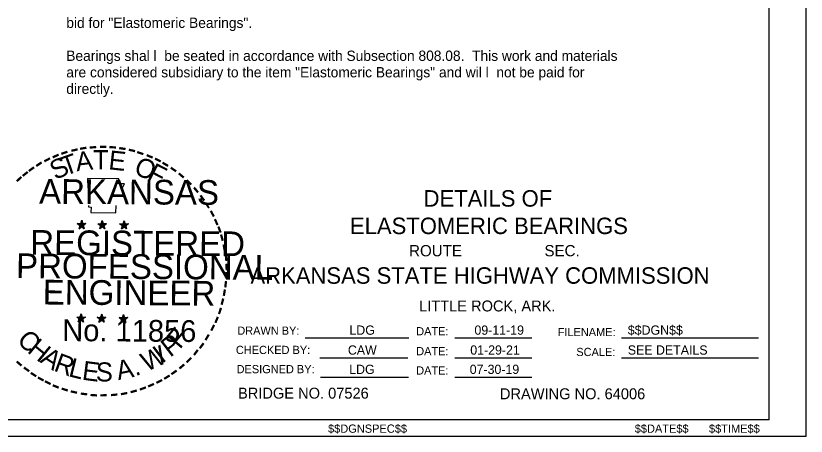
# Model space of a CAD drawing. Extents: x 32334 to 32601, y -901 to -733.
# Drawn here: x 32524.1 to 32600.8, y -900.6 to -859.7 of the extents above; entities that cross this region are included whole.
import ezdxf

# ---------------------------------------------------------------- set-up
doc = ezdxf.new("R2010")
doc.units = 0
for name, color, linetype in [('1', 7, 'Continuous'), ('Level 1', 7, 'Continuous'), ('Level 4', 7, 'Continuous'), ('Level 48', 7, 'Continuous'), ('Level 49', 7, 'Continuous'), ('Level 50', 7, 'Continuous'), ('Level 63', 7, 'Continuous')]:
    doc.layers.add(name, color=color, linetype=linetype)

msp = doc.modelspace()

# ---------------------------------------------------------------- linework, layer by layer
at = {"layer": 'Level 1'}
for q in [(32597.248, -734.586), (32344.303, -898.954)]:
    msp.add_line((32597.248, -898.954), q, dxfattribs=at)
at = {"layer": 'Level 4'}
for p, q in [((32552.203, -891.002), (32562.264, -891.002)), ((32566.721, -891.002), (32574.208, -891.002)), ((32582.925, -891.002), (32596.204, -891.002)), ((32553.623, -892.935), (32562.179, -892.935)), ((32566.721, -892.935), (32574.208, -892.935)), ((32582.925, -892.935), (32596.204, -892.935)), ((32553.683, -894.809), (32562.238, -894.809)), ((32566.721, -894.809), (32574.208, -894.809))]:
    msp.add_line(p, q, dxfattribs=at)
at = {"layer": 'Level 49'}
for p, q in [((32530.079, -879.921), (32530.508, -880.054)), ((32530.079, -879.921), (32530.39, -879.936)), ((32530.079, -879.921), (32530.39, -879.951)), ((32530.079, -879.921), (32530.36, -879.995)), ((32530.079, -879.921), (32530.36, -880.039)), ((32530.079, -879.921), (32530.36, -880.054)), ((32530.079, -879.921), (32530.36, -880.099)), ((32530.256, -880.409), (32530.508, -880.054)), ((32530.256, -880.409), (32530.36, -880.069)), ((32530.256, -880.409), (32530.39, -880.113)), ((32530.256, -880.409), (32530.404, -880.128)), ((32530.256, -880.409), (32530.449, -880.158)), ((32530.256, -880.409), (32530.508, -880.158)), ((32530.508, -879.595), (32530.449, -879.921)), ((32530.508, -879.595), (32530.449, -879.891)), ((32530.508, -879.595), (32530.478, -879.891)), ((32530.508, -880.054), (32530.508, -879.595)), ((32530.508, -879.595), (32530.582, -879.921)), ((32530.508, -879.595), (32530.567, -879.891)), ((32530.508, -879.595), (32530.523, -879.891)), ((32530.922, -879.921), (32530.508, -880.054)), ((32530.76, -880.424), (32530.508, -880.054)), ((32530.76, -880.424), (32530.508, -880.158)), ((32530.922, -879.921), (32530.538, -879.951)), ((32530.76, -880.424), (32530.538, -880.158)), ((32530.922, -879.921), (32530.582, -879.98)), ((32530.922, -879.921), (32530.582, -880.01)), ((32530.76, -880.424), (32530.582, -880.069)), ((32530.76, -880.424), (32530.582, -880.113)), ((32530.76, -880.424), (32530.626, -880.054)), ((32530.922, -879.921), (32530.641, -880.01)), ((32530.922, -879.921), (32530.686, -880.039)), ((32530.922, -879.921), (32530.7, -880.054)), ((32532.077, -879.936), (32532.506, -880.054)), ((32532.077, -879.936), (32532.388, -879.951)), ((32532.077, -879.936), (32532.388, -879.98)), ((32532.077, -879.936), (32532.388, -879.995)), ((32532.077, -879.936), (32532.373, -880.054)), ((32532.077, -879.936), (32532.373, -880.069)), ((32532.077, -879.936), (32532.373, -880.113)), ((32532.254, -880.424), (32532.506, -880.054)), ((32532.254, -880.424), (32532.388, -880.099)), ((32532.254, -880.424), (32532.388, -880.113)), ((32532.254, -880.424), (32532.402, -880.128)), ((32532.254, -880.424), (32532.447, -880.173)), ((32532.254, -880.424), (32532.506, -880.173)), ((32532.506, -879.625), (32532.447, -879.936)), ((32532.506, -879.625), (32532.447, -879.921)), ((32532.506, -879.625), (32532.462, -879.921)), ((32532.506, -880.054), (32532.506, -879.625)), ((32532.506, -879.625), (32532.58, -879.936)), ((32532.506, -879.625), (32532.565, -879.921)), ((32532.506, -879.625), (32532.521, -879.921)), ((32532.92, -879.936), (32532.506, -880.054)), ((32532.758, -880.424), (32532.506, -880.054)), ((32532.758, -880.424), (32532.506, -880.173)), ((32532.92, -879.936), (32532.55, -879.951)), ((32532.758, -880.424), (32532.55, -880.173)), ((32532.92, -879.936), (32532.58, -879.995)), ((32532.92, -879.936), (32532.58, -880.01)), ((32532.758, -880.424), (32532.58, -880.069)), ((32532.758, -880.424), (32532.58, -880.128)), ((32532.758, -880.424), (32532.624, -880.069)), ((32532.92, -879.936), (32532.639, -880.039)), ((32532.92, -879.936), (32532.684, -880.054)), ((32532.92, -879.936), (32532.698, -880.069)), ((32534.193, -879.951), (32534.623, -880.099)), ((32534.193, -879.951), (32534.534, -879.995)), ((32534.193, -879.951), (32534.504, -880.01)), ((32534.193, -879.951), (32534.504, -880.039)), ((32534.193, -879.951), (32534.489, -880.069)), ((32534.193, -879.951), (32534.489, -880.113)), ((32534.193, -879.951), (32534.489, -880.113)), ((32534.356, -880.439), (32534.623, -880.099)), ((32534.356, -880.439), (32534.504, -880.113)), ((32534.356, -880.439), (32534.534, -880.158)), ((32534.356, -880.439), (32534.534, -880.173)), ((32534.356, -880.439), (32534.623, -880.173)), ((32534.623, -879.655), (32534.549, -879.936)), ((32534.623, -879.655), (32534.593, -879.951)), ((32534.623, -879.655), (32534.593, -879.951)), ((32534.623, -880.099), (32534.623, -879.655)), ((32534.623, -879.655), (32534.711, -879.951)), ((32534.623, -879.655), (32534.682, -879.951)), ((32534.623, -879.655), (32534.652, -879.951)), ((32535.037, -879.951), (32534.623, -880.099)), ((32534.859, -880.439), (32534.623, -880.099)), ((32534.859, -880.439), (32534.623, -880.173)), ((32535.037, -879.951), (32534.667, -879.995)), ((32535.037, -879.951), (32534.711, -880.01)), ((32535.037, -879.951), (32534.711, -880.054)), ((32534.859, -880.439), (32534.711, -880.113)), ((32534.859, -880.439), (32534.711, -880.158)), ((32534.859, -880.439), (32534.741, -880.113)), ((32535.037, -879.951), (32534.771, -880.069)), ((32535.037, -879.951), (32534.785, -880.069)), ((32535.037, -879.951), (32534.83, -880.099)), ((32530.256, -880.409), (32530.508, -880.187)), ((32530.76, -880.424), (32530.508, -880.187)), ((32532.254, -880.424), (32532.506, -880.187)), ((32532.758, -880.424), (32532.506, -880.187)), ((32534.356, -880.439), (32534.593, -880.187)), ((32534.356, -880.439), (32534.652, -880.232)), ((32534.859, -880.439), (32534.623, -880.232)), ((32534.859, -880.439), (32534.667, -880.187)), ((32530.02, -889.008), (32530.449, -889.141)), ((32530.02, -889.008), (32530.33, -889.023)), ((32530.02, -889.008), (32530.316, -889.067)), ((32530.02, -889.008), (32530.316, -889.067)), ((32530.02, -889.008), (32530.316, -889.127)), ((32530.02, -889.008), (32530.316, -889.141)), ((32530.02, -889.008), (32530.316, -889.156)), ((32530.168, -889.467), (32530.449, -889.141)), ((32530.168, -889.467), (32530.316, -889.141)), ((32530.168, -889.467), (32530.33, -889.201)), ((32530.168, -889.467), (32530.345, -889.201)), ((32530.168, -889.467), (32530.449, -889.215)), ((32530.168, -889.467), (32530.39, -889.245)), ((32530.168, -889.467), (32530.449, -889.26)), ((32530.449, -888.683), (32530.36, -888.979)), ((32530.449, -888.683), (32530.39, -889.008)), ((32530.449, -888.683), (32530.404, -889.008)), ((32530.686, -889.497), (32530.419, -889.26)), ((32530.449, -889.141), (32530.449, -888.683)), ((32530.449, -888.683), (32530.508, -889.008)), ((32530.449, -888.683), (32530.508, -889.008)), ((32530.449, -888.683), (32530.449, -889.008)), ((32530.863, -889.008), (32530.449, -889.141)), ((32530.686, -889.497), (32530.449, -889.141)), ((32530.686, -889.497), (32530.449, -889.245)), ((32530.686, -889.497), (32530.464, -889.245)), ((32530.863, -889.008), (32530.478, -889.023)), ((32530.863, -889.008), (32530.508, -889.067)), ((32530.863, -889.008), (32530.508, -889.082)), ((32530.686, -889.497), (32530.508, -889.141)), ((32530.686, -889.497), (32530.508, -889.201)), ((32530.863, -889.008), (32530.567, -889.097)), ((32530.686, -889.497), (32530.567, -889.141)), ((32530.863, -889.008), (32530.597, -889.127)), ((32530.863, -889.008), (32530.626, -889.141)), ((32532.018, -889.008), (32532.447, -889.141)), ((32532.018, -889.008), (32532.328, -889.038)), ((32532.018, -889.008), (32532.328, -889.067)), ((32532.018, -889.008), (32532.328, -889.082)), ((32532.018, -889.008), (32532.314, -889.127)), ((32532.018, -889.008), (32532.314, -889.156)), ((32532.018, -889.008), (32532.314, -889.186)), ((32532.166, -889.497), (32532.447, -889.141)), ((32532.166, -889.497), (32532.328, -889.156)), ((32532.166, -889.497), (32532.328, -889.215)), ((32532.166, -889.497), (32532.343, -889.215)), ((32532.166, -889.497), (32532.388, -889.245)), ((32532.166, -889.497), (32532.447, -889.245)), ((32532.166, -889.497), (32532.447, -889.275)), ((32532.447, -888.712), (32532.373, -889.008)), ((32532.447, -888.712), (32532.388, -889.008)), ((32532.447, -888.712), (32532.402, -889.008)), ((32532.684, -889.497), (32532.432, -889.275)), ((32532.447, -889.141), (32532.447, -888.712)), ((32532.447, -888.712), (32532.506, -889.023)), ((32532.447, -888.712), (32532.506, -889.023)), ((32532.447, -888.712), (32532.447, -889.008)), ((32532.846, -889.023), (32532.447, -889.141)), ((32532.684, -889.497), (32532.447, -889.141)), ((32532.684, -889.497), (32532.447, -889.245)), ((32532.684, -889.497), (32532.462, -889.245)), ((32532.846, -889.023), (32532.491, -889.023)), ((32532.846, -889.023), (32532.506, -889.082)), ((32532.846, -889.023), (32532.506, -889.082)), ((32532.684, -889.497), (32532.506, -889.156)), ((32532.684, -889.497), (32532.506, -889.201)), ((32532.846, -889.023), (32532.565, -889.127)), ((32532.684, -889.497), (32532.565, -889.156)), ((32532.846, -889.023), (32532.61, -889.141)), ((32532.846, -889.023), (32532.624, -889.156)), ((32534.134, -889.038), (32534.563, -889.186)), ((32534.134, -889.038), (32534.445, -889.067)), ((32534.134, -889.038), (32534.445, -889.097)), ((32534.134, -889.038), (32534.43, -889.127)), ((32534.134, -889.038), (32534.43, -889.156)), ((32534.134, -889.038), (32534.415, -889.186)), ((32534.134, -889.038), (32534.415, -889.215)), ((32534.297, -889.526), (32534.563, -889.186)), ((32534.297, -889.526), (32534.43, -889.186)), ((32534.297, -889.526), (32534.445, -889.245)), ((32534.297, -889.526), (32534.475, -889.245)), ((32534.297, -889.526), (32534.504, -889.275)), ((32534.297, -889.526), (32534.549, -889.275)), ((32534.297, -889.526), (32534.563, -889.304)), ((32534.563, -888.727), (32534.489, -889.038)), ((32534.563, -888.727), (32534.504, -889.038)), ((32534.563, -888.727), (32534.534, -889.038)), ((32534.8, -889.526), (32534.549, -889.275)), ((32534.8, -889.526), (32534.549, -889.304)), ((32534.563, -889.186), (32534.563, -888.727)), ((32534.563, -888.727), (32534.623, -889.038)), ((32534.563, -888.727), (32534.623, -889.038)), ((32534.563, -888.727), (32534.563, -889.038)), ((32534.978, -889.038), (32534.563, -889.186)), ((32534.8, -889.526), (32534.563, -889.186)), ((32534.8, -889.526), (32534.593, -889.275)), ((32534.978, -889.038), (32534.608, -889.067)), ((32534.978, -889.038), (32534.623, -889.097)), ((32534.978, -889.038), (32534.623, -889.127)), ((32534.8, -889.526), (32534.623, -889.245)), ((32534.8, -889.526), (32534.652, -889.186)), ((32534.8, -889.526), (32534.667, -889.186)), ((32534.978, -889.038), (32534.711, -889.141)), ((32534.978, -889.038), (32534.726, -889.186)), ((32534.978, -889.038), (32534.741, -889.186))]:
    msp.add_line(p, q, dxfattribs=at)
for points in [[(32531.056, -875.54), (32531.1, -876.458)], [(32534.46, -876.458), (32534.652, -876.043), (32534.09, -876.043), (32534.119, -875.57), (32531.056, -875.54)], [(32531.159, -878.175), (32531.174, -878.293), (32531.44, -878.308), (32531.396, -878.855), (32533.808, -878.87), (32533.868, -878.175)], [(32530.508, -879.595), (32530.76, -880.424), (32530.079, -879.921), (32530.922, -879.921), (32530.256, -880.409), (32530.508, -879.595)], [(32532.506, -879.625), (32532.758, -880.424), (32532.077, -879.936), (32532.92, -879.936), (32532.254, -880.424), (32532.506, -879.625)], [(32534.623, -879.655), (32534.859, -880.439), (32534.193, -879.951), (32535.037, -879.951), (32534.356, -880.439), (32534.623, -879.655)], [(32530.449, -888.683), (32530.686, -889.497), (32530.02, -889.008), (32530.863, -889.008), (32530.168, -889.467), (32530.449, -888.683)], [(32532.447, -888.712), (32532.684, -889.497), (32532.018, -889.008), (32532.846, -889.023), (32532.166, -889.497), (32532.447, -888.712)], [(32534.563, -888.727), (32534.8, -889.526), (32534.134, -889.038), (32534.978, -889.038), (32534.297, -889.526), (32534.563, -888.727)]]:
    msp.add_lwpolyline(points, dxfattribs=at)
for centre, radius in [((32530.5, -880.052), 0.207), ((32530.5, -880.052), 0.187), ((32530.5, -880.052), 0.173), ((32530.5, -880.052), 0.159), ((32530.5, -880.052), 0.139), ((32530.5, -880.052), 0.129), ((32530.5, -880.052), 0.119), ((32530.5, -880.052), 0.102), ((32530.5, -880.052), 0.0896), ((32530.5, -880.052), 0.0745), ((32530.5, -880.052), 0.0594), ((32530.5, -880.052), 0.0443), ((32530.5, -880.052), 0.0355), ((32530.5, -880.052), 0.0173), ((32532.502, -880.066), 0.207), ((32532.502, -880.066), 0.187), ((32532.502, -880.066), 0.173), ((32532.502, -880.066), 0.159), ((32532.502, -880.066), 0.139), ((32532.502, -880.066), 0.129), ((32532.502, -880.066), 0.119), ((32532.502, -880.066), 0.102), ((32532.502, -880.066), 0.0896), ((32532.502, -880.066), 0.0745), ((32532.502, -880.066), 0.0594), ((32532.502, -880.066), 0.0443), ((32532.502, -880.066), 0.0355), ((32532.502, -880.066), 0.0173), ((32534.621, -880.095), 0.207), ((32534.621, -880.095), 0.187), ((32534.621, -880.095), 0.173), ((32534.621, -880.095), 0.159), ((32534.621, -880.095), 0.139), ((32534.621, -880.095), 0.129), ((32534.621, -880.095), 0.119), ((32534.621, -880.095), 0.102), ((32534.621, -880.095), 0.0896), ((32534.621, -880.095), 0.0745), ((32534.621, -880.095), 0.0594), ((32534.621, -880.095), 0.0443), ((32534.621, -880.095), 0.0355), ((32534.621, -880.095), 0.0173), ((32530.433, -889.132), 0.207), ((32530.433, -889.132), 0.187), ((32530.433, -889.132), 0.173), ((32530.433, -889.132), 0.159), ((32530.433, -889.132), 0.139), ((32530.433, -889.132), 0.129), ((32530.433, -889.132), 0.119), ((32530.433, -889.132), 0.102), ((32530.433, -889.132), 0.0896), ((32530.433, -889.132), 0.0745), ((32530.433, -889.132), 0.0594), ((32530.433, -889.132), 0.0443), ((32530.433, -889.132), 0.0355), ((32530.433, -889.132), 0.0173), ((32532.434, -889.146), 0.207), ((32532.434, -889.146), 0.187), ((32532.434, -889.146), 0.173), ((32532.434, -889.146), 0.159), ((32532.434, -889.146), 0.139), ((32532.434, -889.146), 0.129), ((32532.434, -889.146), 0.119), ((32532.434, -889.146), 0.102), ((32532.434, -889.146), 0.0896), ((32532.434, -889.146), 0.0745), ((32532.434, -889.146), 0.0594), ((32532.434, -889.146), 0.0443), ((32532.434, -889.146), 0.0355), ((32532.434, -889.146), 0.0173), ((32534.553, -889.175), 0.207), ((32534.553, -889.175), 0.187), ((32534.553, -889.175), 0.173), ((32534.553, -889.175), 0.159), ((32534.553, -889.175), 0.139), ((32534.553, -889.175), 0.129), ((32534.553, -889.175), 0.119), ((32534.553, -889.175), 0.102), ((32534.553, -889.175), 0.0896), ((32534.553, -889.175), 0.0745), ((32534.553, -889.175), 0.0594), ((32534.553, -889.175), 0.0443), ((32534.553, -889.175), 0.0355), ((32534.553, -889.175), 0.0173)]:
    msp.add_circle(centre, radius, dxfattribs=at)
at = {"layer": 'Level 63'}
msp.add_lwpolyline([(32334.207, -900.55), (32600.848, -900.55), (32600.848, -732.974), (32334.207, -732.974)], close=True, dxfattribs=at)

# ---------------------------------------------------------------- texts
at = {"layer": '1'}
for s, p in [('bid for "Elastomeric Bearings".', (32529.01, -860.925)), ('Bearings shal l  be seated in accordance with Subsection 808.08.  This work and materials', (32529.01, -864.125)), ('are considered subsidiary to the item "Elastomeric Bearings" and wil l  not be paid for ', (32529.01, -865.725)), ('directly.', (32529.01, -867.325))]:
    msp.add_text(s, height=1, dxfattribs=at).set_placement(p)
at = {"layer": 'Level 4'}
for s, height, p in [('DETAILS OF', 1.5999, (32563.703, -878.27)), ('ELASTOMERIC BEARINGS', 1.59989, (32556.553, -880.936)), ('ROUTE', 1.0951, (32562.297, -883.093)), ('SEC.', 1.0951, (32575.438, -883.093)), ('ARKANSAS STATE HIGHWAY COMMISSION', 1.59988, (32546.893, -885.755)), ('LITTLE ROCK, ARK.', 1.06089, (32563.264, -888.443)), ('DRAWN BY:', 0.7957, (32545.615, -890.702)), ('DATE:', 0.7957, (32562.983, -890.762)), ('FILENAME:', 0.7957, (32576.723, -890.839)), ('CHECKED BY:', 0.79566, (32545.478, -892.576)), ('DATE:', 0.7957, (32562.983, -892.696)), ('SCALE:', 0.7957, (32578.528, -892.773)), ('DESIGNED BY:', 0.79566, (32545.547, -894.441)), ('DATE:', 0.7957, (32562.983, -894.569)), ('BRIDGE NO. 07526', 1.06089, (32545.684, -896.905)), ('DRAWING NO. 64006', 1.06089, (32571.11, -896.965))]:
    msp.add_text(s, height=height, dxfattribs=at).set_placement(p)
for s, height, p in [('LDG', 0.8984, (32556.5, -890.704)), ('09-11-19', 0.8984, (32568.639, -890.703)), ('$$DGN$$', 0.8984, (32583.53, -890.703)), ('CAW', 0.8984, (32556.349, -892.638)), ('01-29-21', 0.8984, (32568.234, -892.636)), ('SEE DETAILS', 0.89843, (32583.53, -892.636)), ('LDG', 0.8984, (32556.48, -894.513)), ('07-30-19', 0.8984, (32568.178, -894.51))]:
    msp.add_text(s, height=height, rotation=0.0001, dxfattribs=at).set_placement(p)
at = {"layer": 'Level 48'}
for s, height, p in [('$$DGNSPEC$$', 0.80002, (32554.423, -900.218)), ('$$DATE$$', 0.8, (32584.199, -900.218)), ('$$TIME$$', 0.8, (32591.408, -900.218))]:
    msp.add_text(s, height=height, dxfattribs=at).set_placement(p)
at = {"layer": 'Level 49'}
for s, height, rotation, p in [('-', 1.919, 9.82175, (32530.36, -873.409)), ('-', 1.918, 5.49922, (32531.248, -873.291)), ('-', 1.918, 359.78863, (32532.166, -873.202)), ('-', 1.919, 357.34544, (32533.054, -873.231)), ('-', 1.919, 351.76412, (32533.927, -873.305)), ('-', 1.918, 23.90961, (32527.888, -874.208)), ('-', 1.918, 18.77848, (32528.658, -873.883)), ('-', 1.918, 13.23255, (32529.561, -873.601)), ('-', 1.919, 346.80729, (32534.8, -873.439)), ('-', 1.919, 341.9386, (32535.555, -873.646)), ('-', 1.919, 337.45749, (32536.428, -873.912)), ('-', 1.919, 33.66597, (32526.408, -875.007)), ('-', 1.918, 28.39422, (32527.134, -874.578)), ('-', 1.918, 333.72349, (32537.198, -874.223)), ('-', 1.918, 329.24329, (32537.879, -874.578)), ('-', 1.918, 35.83414, (32525.713, -875.481)), ('-', 1.918, 325.46506, (32538.648, -875.037)), ('-', 1.918, 42.56464, (32524.618, -876.428)), ('-', 1.918, 38.55306, (32525.15, -875.94)), ('-', 1.919, 320.13211, (32539.373, -875.54)), ('ARKANSAS', 2.3981, 359.6024, (32526.364, -877.982)), ('-', 1.919, 315.18099, (32540.099, -876.132)), ('-', 1.918, 309.48212, (32540.765, -876.798)), ('-', 1.918, 306.25458, (32541.371, -877.523)), ('-', 1.679, 303.27769, (32541.963, -878.219)), ('-', 1.919, 299.27075, (32542.333, -878.944)), ('-', 1.918, 294.26519, (32542.718, -879.684)), ('-', 1.918, 290.17523, (32543.044, -880.35)), ('REGISTERED', 2.3981, 359.6024, (32525.506, -882.94)), ('-', 1.918, 284.72566, (32543.295, -881.061)), ('-', 1.919, 280.15174, (32543.532, -881.963)), ('PROFESSIONAL', 2.39814, 359.6024, (32524.129, -885.205)), ('-', 1.919, 276.19856, (32543.739, -882.881)), ('-', 1.919, 273.93251, (32543.799, -883.754)), ('-', 1.918, 269.54307, (32543.828, -884.494)), ('ENGINEER', 2.3981, 359.6024, (32526.719, -887.765)), ('-', 1.918, 263.1196, (32543.799, -885.293)), ('-', 1.919, 260.59769, (32543.695, -886.078)), ('-', 1.918, 255.365, (32543.562, -886.892)), ('-', 1.919, 252.47049, (32543.355, -887.765)), ('No. 11856', 2.1102, 359.6024, (32528.614, -891.317)), ('-', 1.918, 247.49106, (32543.088, -888.579)), ('-', 1.919, 244.22211, (32542.748, -889.319)), ('-', 1.919, 238.67365, (32542.274, -890.207)), ('-', 1.919, 233.44764, (32541.815, -890.991)), ('-', 1.919, 233.44764, (32541.253, -891.643)), ('-', 1.918, 138.53622, (32525.239, -893.226)), ('-', 1.918, 225.36773, (32540.691, -892.338)), ('-', 1.918, 144.24874, (32525.935, -893.715)), ('-', 1.918, 220.68749, (32540.069, -892.945)), ('-', 1.919, 147.69218, (32526.586, -894.173)), ('-', 1.918, 151.17279, (32527.267, -894.558)), ('-', 1.919, 211.85149, (32538.752, -893.966)), ('-', 1.918, 215.33873, (32539.388, -893.507)), ('-', 1.918, 154.20259, (32527.918, -894.869)), ('-', 1.919, 158.16361, (32528.658, -895.195)), ('-', 1.918, 203.85401, (32537.331, -894.751)), ('-', 1.919, 206.95924, (32538.086, -894.381)), ('-', 1.918, 162.40066, (32529.487, -895.446)), ('-', 1.919, 167.15791, (32530.33, -895.639)), ('-', 1.919, 190.88816, (32534.904, -895.609)), ('-', 1.918, 195.07669, (32535.777, -895.372)), ('-', 1.918, 200.32082, (32536.591, -895.076)), ('-', 1.919, 172.71786, (32531.248, -895.772)), ('-', 1.919, 176.12067, (32532.151, -895.861)), ('-', 1.919, 181.19416, (32533.039, -895.831)), ('-', 1.918, 185.41906, (32534.016, -895.757))]:
    msp.add_text(s, height=height, rotation=rotation, dxfattribs=at).set_placement(p)
at = {"layer": 'Level 50'}
for s, rotation, p in [('T', 19.33651, (32528.88, -875.303)), ('A', 6.55971, (32530.02, -874.845)), ('T', 0.17131, (32531.618, -874.637)), ('E', 353.7829, (32533.054, -874.637)), ('S', 25.72492, (32527.962, -875.718)), ('O', 338.75668, (32535.481, -875.081)), ('F', 332.36827, (32536.754, -875.599)), ('F', 50.15382, (32540.039, -892.175)), ('C', 314.32777, (32524.129, -891.317)), ('P', 37.37701, (32539.092, -892.945)), ('H', 320.71618, (32525.136, -892.353)), ('W', 24.60021, (32536.798, -894.321)), ('A', 327.10458, (32526.379, -893.33)), ('I', 37.37701, (32538.308, -893.552)), ('R', 339.88139, (32527.711, -894.173)), ('L', 346.26979, (32529.146, -894.721)), ('A', 11.8234, (32534.06, -895.121)), ('E', 352.65819, (32530.478, -895.061)), ('S', 359.04659, (32531.87, -895.224)), ('.', 18.21181, (32535.718, -894.736))]:
    msp.add_text(s, height=1.85, rotation=rotation, dxfattribs=at).set_placement(p)

doc.saveas('drawing.dxf')
